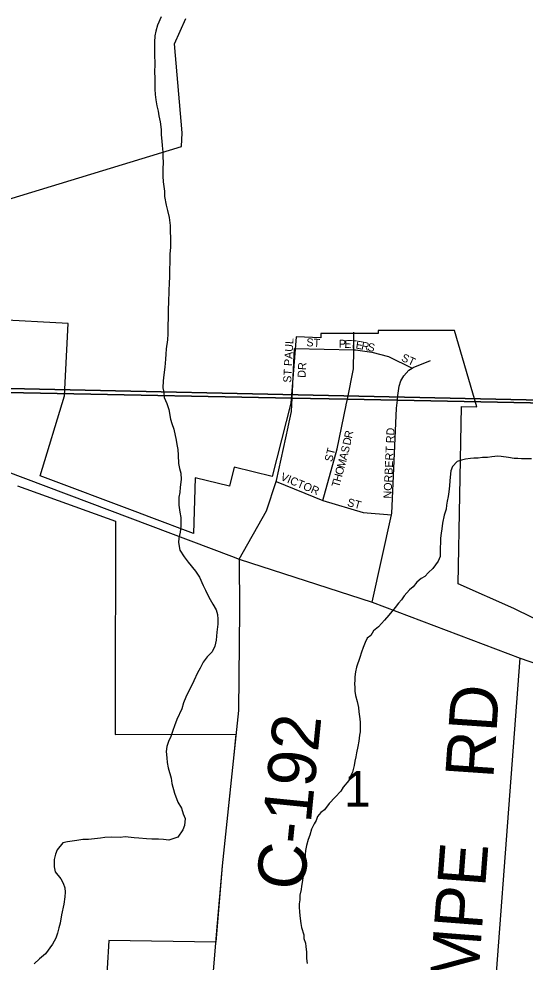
# Model space of a CAD drawing. Extents: x 1588073 to 2013523, y 1090242 to 1357120.
# Drawn here: x 1807066 to 1810221, y 1214356 to 1220235 of the extents above; entities that cross this region are included whole.
import ezdxf

# ---------------------------------------------------------------- set-up
doc = ezdxf.new("R2010")
doc.units = 0
for name, color, linetype in [('GM_X_Corporation', 7, 'Continuous'), ('GM_X_County_Road', 7, 'Continuous'), ('GM_X_County_Road_Text', 7, 'Continuous'), ('GM_X_Minor_River', 7, 'Continuous'), ('GM_X_Section', 7, 'Continuous'), ('GM_X_Section_Text', 7, 'Continuous'), ('GM_X_Township', 7, 'Continuous'), ('GM_X_Township_Road', 7, 'Continuous'), ('GM_X_Township_Road_Text', 7, 'Continuous'), ('GM_X_Township_Subdivision', 7, 'Continuous'), ('GM_X_Township_Subdivision_Text', 7, 'Continuous')]:
    doc.layers.add(name, color=color, linetype=linetype)

msp = doc.modelspace()

# ---------------------------------------------------------------- linework, layer by layer
at = {"layer": 'GM_X_Corporation'}
for points in [[(1806949.5, 1219093.5), (1808080.2, 1219439.5), (1808084.6, 1219523.9), (1808035.9, 1220079.1), (1808106.4, 1220237.5)], [(1810378.9, 1216448.7), (1810150.6, 1216560.1), (1809804.4, 1216714.2), (1809823.7, 1217819.1), (1809920.6, 1217817.4), (1809781.3, 1218293.5), (1809306.1, 1218293.4), (1809306.1, 1218273.3), (1809161, 1218273.3), (1808948.9, 1218273.3), (1808948.2, 1218247.2), (1808794.7, 1218252.9), (1808760.2, 1217839.7), (1808643.7, 1217382.1), (1808407, 1217441), (1808378.7, 1217322.3), (1808164.7, 1217373.5), (1808153.6, 1217026.5), (1807878.8, 1217131.2), (1807807.8, 1217158.2), (1807198.1, 1217386), (1807349.4, 1217885.9), (1807372.9, 1218337), (1806911.3, 1218361.1)], [(1807057.7, 1217324.6), (1807667.2, 1217103.5), (1807666, 1215932.2), (1807666.1, 1215775.7), (1808419.1, 1215777.1), (1808405.6, 1215647.9), (1808333, 1214955.6), (1808292.7, 1214479.7), (1807627.4, 1214491.2), (1807595.4, 1213967.2)]]:
    msp.add_lwpolyline(points, dxfattribs=at)
at = {"layer": 'GM_X_County_Road'}
for points in [[(1806345.8, 1217657), (1808391.2, 1216885.7)], [(1808391.2, 1216885.7), (1808391.2, 1216885.7), (1808439.9, 1216867.3), (1809267.5, 1216599.4)], [(1808439.9, 1216867.3), (1808440.8, 1216550.4), (1808434.8, 1215924.7), (1808430.6, 1215884.7)], [(1809267.5, 1216599.4), (1810190, 1216249.6), (1812026.1, 1215616.5)], [(1808430.6, 1215884.7), (1808333, 1214955.6), (1808302.2, 1214597.8)], [(1808302.2, 1214597.8), (1808261.6, 1214126.4), (1808248.3, 1213924.1), (1808250.6, 1213813.7), (1808300.5, 1213677.8)]]:
    msp.add_lwpolyline(points, dxfattribs=at)
at = {"layer": 'GM_X_Minor_River'}
for points in [[(1807952.9, 1220246.8), (1807930.3, 1220194.9), (1807919.9, 1220159), (1807913.5, 1220129), (1807911.1, 1220088.9), (1807910.6, 1220044.8), (1807912.2, 1220012.8), (1807913.6, 1219954.6), (1807910.9, 1219900.5), (1807912.6, 1219870.4), (1807914.1, 1219828.3), (1807913.8, 1219796.3), (1807915.4, 1219764.2), (1807919, 1219730.1), (1807926.6, 1219691.9), (1807934.2, 1219659.7), (1807937.9, 1219629.6), (1807947.5, 1219593.4), (1807953, 1219545.3), (1807952.6, 1219511.2), (1807956.2, 1219473.1), (1807959.8, 1219445), (1807963.4, 1219404.9), (1807963, 1219374.8), (1807964.6, 1219338.7), (1807962.2, 1219300.7), (1807963.7, 1219254.6), (1807965.3, 1219218.5), (1807969, 1219190.3), (1807972.6, 1219160.2), (1807974.3, 1219128.2), (1807983.7, 1219073.9), (1807993.3, 1219039.8), (1808002.8, 1218997.6), (1808008.3, 1218947.4), (1808009.8, 1218907.3), (1808011.4, 1218873.2)], [(1808011.4, 1218873.2), (1808010.7, 1218811.1), (1808006.2, 1218769), (1808004.6, 1218622.7), (1808002.2, 1218592.7), (1807999.6, 1218538.6), (1807998.8, 1218470.5), (1807996.3, 1218424.4), (1807994.6, 1218272.1), (1807992.1, 1218234), (1807983.5, 1218178), (1807981.1, 1218145.9), (1807980.8, 1218113.9), (1807976.2, 1218063.8), (1807969.6, 1218015.8), (1807965.2, 1217979.8), (1807962.7, 1217935.7), (1807968.4, 1217907.6), (1807972, 1217875.5), (1807987.6, 1217837.2), (1808001.2, 1217801), (1808010.6, 1217740.8), (1808020.3, 1217712.6), (1808031.9, 1217678.4), (1808047.1, 1217610.1), (1808050.8, 1217582), (1808056.4, 1217549.9), (1808058.1, 1217515.8), (1808061.5, 1217463.6), (1808067.1, 1217431.5), (1808074.8, 1217403.3), (1808078.4, 1217363.2), (1808071.8, 1217317.2), (1808069.4, 1217283.1), (1808063.1, 1217253.1), (1808062.5, 1217203), (1808070.1, 1217160.9), (1808075.7, 1217126.7), (1808075.1, 1217072.6), (1808070.6, 1217036.6), (1808062.2, 1216998.6), (1808059.9, 1216970.6), (1808069.4, 1216924.4), (1808096.9, 1216882), (1808120.6, 1216849.7), (1808166, 1216793.1), (1808191.6, 1216754.7), (1808215.1, 1216704.3), (1808228.7, 1216674.1), (1808250.3, 1216629.8), (1808275.8, 1216587.4), (1808295.5, 1216551.1), (1808303.1, 1216523), (1808306.8, 1216492.9), (1808306.5, 1216462.8), (1808299.9, 1216412.8), (1808295.3, 1216362.8), (1808286.9, 1216324.8), (1808270.4, 1216288.9), (1808240, 1216259.1), (1808213.6, 1216225.3), (1808195.2, 1216187.4), (1808178.8, 1216159.6), (1808156.2, 1216109.7), (1808107, 1216008), (1808092.6, 1215972.1), (1808082.1, 1215934.1), (1808051.3, 1215868.3), (1808034.9, 1215828.4), (1808024.5, 1215800.4), (1808012.1, 1215762.5), (1807997.7, 1215730.6), (1807987.3, 1215700.6), (1807983, 1215668.6), (1807988.5, 1215628.4), (1807990.2, 1215600.4), (1807995.8, 1215566.2), (1808015.1, 1215501.9), (1808018.8, 1215469.8), (1808036.1, 1215409.5), (1808057.5, 1215353.1), (1808079.1, 1215314.8), (1808090.7, 1215280.6), (1808102.4, 1215250.4), (1808097.9, 1215208.4), (1808087.6, 1215180.4), (1808057, 1215134.7), (1808000.7, 1215115.2), (1807966.7, 1215119.6), (1807936.7, 1215121.9), (1807894.6, 1215122.4), (1807860.6, 1215124.7), (1807812.6, 1215129.2), (1807784.6, 1215129.6), (1807728.5, 1215136.2), (1807696.5, 1215132.5), (1807642.4, 1215135.1), (1807602.3, 1215133.5), (1807574.2, 1215127.8), (1807500, 1215120.6), (1807464, 1215120.9)], [(1810072.9, 1217508.3), (1810050.9, 1217508.5), (1810014.8, 1217504.9), (1809986.7, 1217501.1), (1809954.6, 1217501.5), (1809928.6, 1217497.8), (1809902.5, 1217496), (1809880.4, 1217494.3), (1809850.4, 1217490.6), (1809824.3, 1217484.9), (1809798.1, 1217477.1), (1809767.7, 1217445.4), (1809757.4, 1217417.4), (1809755, 1217379.4), (1809752.7, 1217355.3), (1809750.3, 1217325.3), (1809745.9, 1217287.3), (1809741.6, 1217257.2), (1809735.2, 1217229.2), (1809730.9, 1217203.2), (1809728.6, 1217179.2), (1809716.2, 1217141.3), (1809705.6, 1217091.3), (1809701.2, 1217057.2), (1809698.9, 1217029.2), (1809694.6, 1216999.2), (1809694.3, 1216977.1), (1809691.8, 1216931.1), (1809691.3, 1216885), (1809678.9, 1216855.1), (1809646.3, 1216809.3), (1809620, 1216783.5), (1809595.7, 1216759.7), (1809573.5, 1216747.9), (1809547.2, 1216724.2), (1809522.8, 1216694.4), (1809500.6, 1216676.6), (1809468.1, 1216638.8), (1809449.8, 1216615), (1809431.6, 1216593.1), (1809411.2, 1216565.3), (1809372.6, 1216517.6), (1809344.2, 1216487.8), (1809307.7, 1216446.1), (1809275.4, 1216420.4), (1809259, 1216392.5), (1809236.8, 1216374.7), (1809224.5, 1216348.8), (1809212.1, 1216316.9), (1809201.7, 1216286.9), (1809191.4, 1216255), (1809170.7, 1216195.1), (1809164.3, 1216165.1), (1809160, 1216135), (1809159.7, 1216113), (1809157.5, 1216091), (1809159.2, 1216066.9), (1809160.9, 1216044.8), (1809164.6, 1216018.7), (1809174.2, 1215980.6), (1809181.8, 1215942.4), (1809185.5, 1215916.3), (1809191, 1215872.1), (1809192.8, 1215850.1), (1809192.1, 1215792), (1809189.8, 1215769.9), (1809185.4, 1215733.9), (1809179, 1215699.9), (1809170.6, 1215659.9), (1809166.3, 1215635.9), (1809160, 1215607.9), (1809155.7, 1215581.9), (1809145.2, 1215539.9), (1809132.9, 1215514), (1809122.5, 1215488.1), (1809088, 1215446.3), (1809071.7, 1215422.4), (1809037.3, 1215384.7), (1809000.8, 1215345), (1808970.3, 1215305.3), (1808948, 1215289.5), (1808927.7, 1215263.6), (1808919.4, 1215239.7), (1808907.2, 1215217.8), (1808890.8, 1215183.9), (1808880.3, 1215147.9), (1808868, 1215120), (1808857.6, 1215082), (1808853.2, 1215052), (1808850.9, 1215026), (1808848.5, 1214989.9), (1808844.2, 1214965.9), (1808839.8, 1214933.9), (1808837.6, 1214911.9), (1808835.2, 1214881.8), (1808830.9, 1214851.8), (1808826.6, 1214829.8), (1808824.4, 1214807.8), (1808818, 1214773.8), (1808817.7, 1214743.7), (1808813.4, 1214719.7)], [(1810261, 1217492.2), (1810198.9, 1217492.9), (1810174.9, 1217495.1), (1810152.9, 1217495.4), (1810116.9, 1217501.8), (1810072.9, 1217508.3)], [(1807464, 1215120.9), (1807427.9, 1215113.3), (1807397.8, 1215109.6), (1807369.7, 1215105.9), (1807339.6, 1215100.2), (1807305, 1215056.5), (1807294.7, 1215028.6), (1807286.3, 1214996.6), (1807285.8, 1214950.5), (1807291.4, 1214918.4), (1807327, 1214875.9), (1807342.7, 1214847.7), (1807352.4, 1214819.5), (1807354.1, 1214791.4), (1807351.8, 1214763.4), (1807345.2, 1214717.4), (1807332.5, 1214651.3), (1807323.9, 1214599.3), (1807315.5, 1214569.4), (1807307.1, 1214537.4), (1807296.8, 1214505.4), (1807276.3, 1214467.6), (1807231.6, 1214407.9), (1807195.1, 1214376.2), (1807160.7, 1214344.5)], [(1808813.4, 1214719.7), (1808813.1, 1214695.7), (1808814.8, 1214671.6), (1808816.5, 1214645.5), (1808824, 1214597.3), (1808827.7, 1214571.2), (1808841.2, 1214527), (1808842.9, 1214502.9), (1808852.6, 1214474.8), (1808854.4, 1214452.7), (1808858, 1214418.6), (1808859.6, 1214378.5), (1808863.2, 1214346.4)]]:
    msp.add_lwpolyline(points, dxfattribs=at)
at = {"layer": 'GM_X_Section'}
for points in [[(1812168.6, 1223159.6), (1812172.2, 1223091.5), (1812121.6, 1217818.8), (1806815.3, 1217935.6), (1806959.3, 1223121.7)], [(1806367.2, 1217950.4), (1806815.3, 1217935.6), (1812121.6, 1217818.8), (1811932.1, 1213063.2), (1811927.2, 1212905.2), (1806128.5, 1213321.2)]]:
    msp.add_lwpolyline(points, close=True, dxfattribs=at)
at = {"layer": 'GM_X_Township'}
for points in [[(1800529.6, 1218049.4), (1802043.9, 1218004), (1802568.9, 1217993.7), (1802868.2, 1217987.8), (1803285.1, 1217979.6), (1803767.3, 1217970), (1804011.8, 1217965.2), (1804272.6, 1217960.1), (1804384.2, 1217957.9), (1805067.4, 1217944.4), (1805488.9, 1217936.1), (1805838.6, 1217929.2), (1808769.3, 1217871.3), (1809113.8, 1217864.5), (1809425.1, 1217858.4), (1812123.4, 1217805.2)], [(1812123.4, 1217805.2), (1809425.1, 1217858.4), (1809113.8, 1217864.5), (1808769.3, 1217871.3), (1805838.6, 1217929.2), (1805488.9, 1217936.1), (1805067.4, 1217944.4), (1804384.2, 1217957.9), (1804272.6, 1217960.1), (1804011.8, 1217965.2), (1803767.3, 1217970), (1803285.1, 1217979.6), (1802868.2, 1217987.8), (1802568.9, 1217993.7), (1802043.9, 1218004), (1800529.6, 1218049.4)]]:
    msp.add_lwpolyline(points, dxfattribs=at)
at = {"layer": 'GM_X_Township_Road'}
msp.add_lwpolyline([(1809973.1, 1213351), (1810190, 1216249.6)], dxfattribs=at)
at = {"layer": 'GM_X_Township_Subdivision'}
for points in [[(1809106.2, 1217827.9), (1809106.5, 1217829.3), (1809113.7, 1217864.6), (1809152.5, 1218053.3), (1809153.4, 1218171.7), (1809154.2, 1218282)], [(1808744.2, 1217690.5), (1808744.5, 1217691.8), (1808765.4, 1217788.8), (1808769.3, 1217871.4), (1808783.7, 1218179.6)], [(1808783.7, 1218179.6), (1809153.4, 1218171.7), (1809164.4, 1218171.5), (1809265.3, 1218156.7), (1809370.3, 1218130.1), (1809517.7, 1218058)], [(1809428.6, 1217888.1), (1809435.5, 1217946.5), (1809445.9, 1217978.5), (1809464.6, 1218010.3), (1809495.5, 1218044.7), (1809517.7, 1218058), (1809523.5, 1218061.4), (1809632.5, 1218105.8)], [(1809267.5, 1216599.4), (1809388.7, 1217144.1), (1809390.6, 1217153), (1809419.2, 1217808.4), (1809425.1, 1217858.4), (1809428.6, 1217888.1), (1809428.6, 1217888.1)], [(1808960.9, 1217234.1), (1809050.3, 1217555.6), (1809106.2, 1217827.9)], [(1808439.9, 1216867.3), (1808609.1, 1217169.5), (1808670.5, 1217351.7), (1808672.3, 1217357), (1808744.2, 1217690.5)], [(1808670.5, 1217351.7), (1808960.9, 1217234.1), (1809212.3, 1217157.8), (1809388.7, 1217144.1)]]:
    msp.add_lwpolyline(points, dxfattribs=at)

# ---------------------------------------------------------------- texts
at = {"layer": 'GM_X_County_Road_Text'}
msp.add_text('C-192', height=300, rotation=84.28056, dxfattribs=at).set_placement((1808843.2, 1214796.5))
at = {"layer": 'GM_X_Section_Text'}
msp.add_text('1', height=221, rotation=0.00001, dxfattribs=at).set_placement((1809093.6, 1215325.7))
at = {"layer": 'GM_X_Township_Road_Text'}
for s, rotation, p in [('RD', 86.05506, (1810022.4, 1215496.1)), ('TIMPE', 85.63713, (1809899.3, 1213864.5))]:
    msp.add_text(s, height=300, rotation=rotation, dxfattribs=at).set_placement(p)
at = {"layer": 'GM_X_Township_Subdivision_Text'}
for s, rotation, p in [('ST PAUL', 86.93517, (1808763, 1217965.9)), ('ST', 356.42537, (1808856.6, 1218194.8)), ('P', 357.49917, (1809058.8, 1218186)), ('E', 357.48552, (1809093.9, 1218184.5)), ('T', 356.11685, (1809128.8, 1218183)), ('E', 350.75326, (1809162.7, 1218180.7)), ('R', 348.81631, (1809197, 1218175.1)), ('S', 348.68203, (1809235.8, 1218167.5)), ('ST', 334.98231, (1809445.2, 1218105.9)), ('DR', 86.98901, (1808852.4, 1217996.6)), ('R', 77.88184, (1809141, 1217616.9)), ('NORBERT RD', 87.39635, (1809387.8, 1217244.2)), ('D', 77.44539, (1809131.3, 1217573.6)), ('ST', 75.95732, (1809018.5, 1217470.5)), ('S', 76.30274, (1809119.7, 1217525.4)), ('M', 74.81215, (1809094.6, 1217430.5)), ('A', 75.53989, (1809108.6, 1217482.1)), ('O', 74.62506, (1809082.8, 1217387.9)), ('VICTOR', 337.37981, (1808692.4, 1217362.5)), ('T', 74.65502, (1809061.9, 1217311.5)), ('H', 74.64903, (1809071.2, 1217345.5)), ('ST', 345.06904, (1809109.2, 1217200.1))]:
    msp.add_text(s, height=50, rotation=rotation, dxfattribs=at).set_placement(p)

doc.saveas('drawing.dxf')
